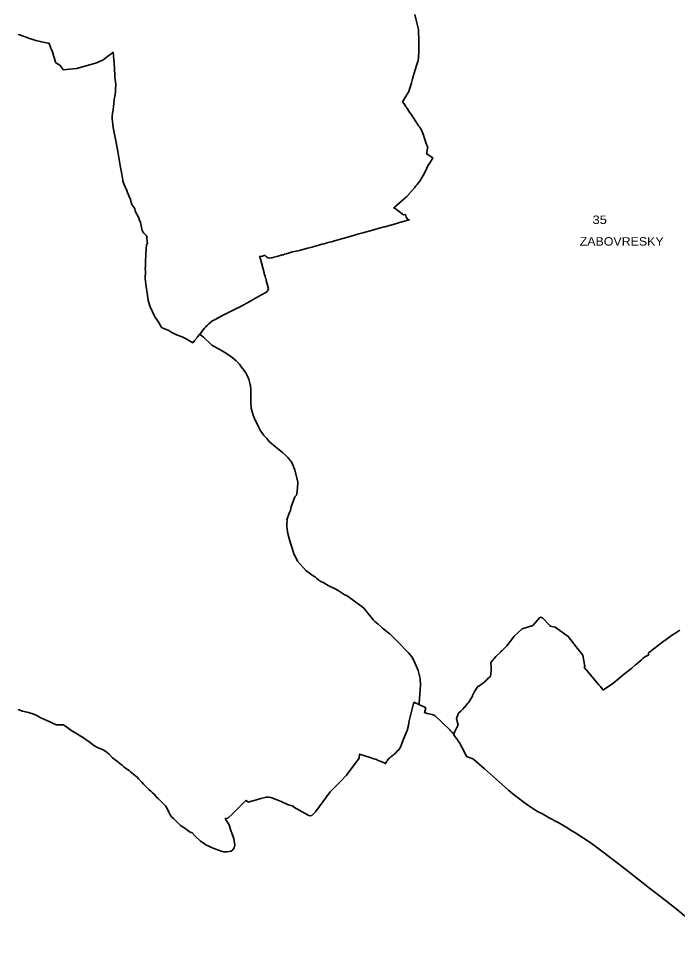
# Model space of a CAD drawing. Extents: x -610940 to -588976, y -1170376 to -1149800.
# Drawn here: x -602206 to -600249, y -1160526 to -1157770 of the extents above; entities that cross this region are included whole.
import ezdxf

# ---------------------------------------------------------------- set-up
doc = ezdxf.new("R2010")
doc.units = 0
doc.header["$LTSCALE"] = 10
doc.layers.add('54', color=7, linetype='Continuous', lineweight=35)
doc.layers.add('55', color=7, linetype='Continuous')
doc.layers.add('56', color=7, linetype='Continuous')

msp = doc.modelspace()

# ---------------------------------------------------------------- linework, layer by layer
at = {"layer": '54'}
for p, q in [((-600256.89, -1159594.38), (-600242.07, -1159585.3)), ((-600761.14, -1159636.5), (-600755.67, -1159631.06)), ((-600318.84, -1159639.11), (-600306.21, -1159629.48)), ((-600803.69, -1159681.2), (-600788.7, -1159663.5)), ((-600788.7, -1159663.5), (-600775.01, -1159650.19)), ((-600775.01, -1159650.19), (-600774.45, -1159649.64)), ((-600774.45, -1159649.64), (-600769.94, -1159645.18)), ((-600346.15, -1159664.1), (-600336.38, -1159659.02)), ((-600335.61, -1159654.46), (-600335.55, -1159653.86)), ((-600335.55, -1159653.86), (-600335.41, -1159653.29)), ((-600335.2, -1159652.76), (-600335.41, -1159653.29)), ((-600335.2, -1159652.76), (-600334.93, -1159652.27)), ((-600334.93, -1159652.27), (-600334.53, -1159651.75)), ((-600334.13, -1159651.34), (-600334.53, -1159651.75)), ((-600384.88, -1159697.23), (-600373.9, -1159688.12)), ((-600464.78, -1159759.14), (-600442.27, -1159744.24)), ((-600464.78, -1159759.14), (-600469.58, -1159763.19)), ((-600876.64, -1159807.7), (-600871.66, -1159801.73)), ((-600866.79, -1159795.54), (-600863.14, -1159789.05)), ((-600898.49, -1159830.42), (-600892.88, -1159824.83)), ((-600892.88, -1159824.83), (-600887.2, -1159819.14)), ((-600887.2, -1159819.14), (-600881.69, -1159813.64)), ((-600909.7, -1159901.75), (-600913.09, -1159895.14)), ((-600904.86, -1159907.75), (-600909.7, -1159901.75)), ((-600895.74, -1159920.66), (-600900.15, -1159914.02)), ((-600470.21, -1160243.42), (-600501.91, -1160220.12)), ((-600416, -1160285.12), (-600470.21, -1160243.42)), ((-600397.56, -1160299.41), (-600416, -1160285.12))]:
    msp.add_line(p, q, dxfattribs=at)
for points in [[(-601029.74, -1157758.56), (-601025.69, -1157774.47), (-601022.58, -1157786.7), (-601019.49, -1157798.83), (-601018.42, -1157803.03), (-601018.14, -1157814.11), (-601017.81, -1157827.13), (-601017.46, -1157841.15)], [(-602207, -1157817.24), (-602202.54, -1157818.76), (-602195.15, -1157821.26), (-602194.27, -1157821.58), (-602192.13, -1157822.29), (-602180.25, -1157826.63), (-602179.38, -1157826.95), (-602178.75, -1157827.18), (-602176.41, -1157828.03), (-602166.9, -1157831.54), (-602166.14, -1157831.49), (-602160.68, -1157833.52), (-602155.24, -1157834.82), (-602154.31, -1157835.04), (-602153.54, -1157835.23), (-602141.7, -1157838.07), (-602138.09, -1157838.94)], [(-602138.09, -1157838.94), (-602118.22, -1157843.5), (-602115.24, -1157844.18), (-602109.73, -1157858.46), (-602107.49, -1157864.27), (-602099.56, -1157888.35), (-602095.84, -1157899.63), (-602095.28, -1157901.35), (-602083.71, -1157908.5), (-602074.91, -1157920.41), (-602073.32, -1157922.56), (-602033.8, -1157918.16), (-601998.69, -1157908.55), (-601974.08, -1157901.25), (-601969.3, -1157899.83), (-601954.96, -1157893.04), (-601937.8, -1157879.58), (-601932.44, -1157875.37), (-601931.46, -1157874.61), (-601925.53, -1157869.96), (-601922.48, -1157903.68), (-601921.22, -1157917.89), (-601920.75, -1157924.87), (-601920.28, -1157931.99), (-601919.92, -1157944.69), (-601918.05, -1157956.51), (-601917.55, -1157967.5), (-601917.69, -1157978.93), (-601917.93, -1157989.72), (-601920.13, -1158000.1), (-601921.64, -1158010.6), (-601923.02, -1158022.44), (-601924.01, -1158030.93), (-601925.13, -1158041.26), (-601927.36, -1158050.84), (-601927.84, -1158058.99), (-601927.85, -1158067.25), (-601927.1, -1158075.33), (-601925.42, -1158093.35), (-601916.59, -1158137.77)], [(-601017.46, -1157841.15), (-601017.09, -1157855.84), (-601017.05, -1157857.4), (-601017.14, -1157869.11), (-601017.17, -1157872.59), (-601018.03, -1157880.29), (-601018.29, -1157882.64), (-601018.56, -1157885.13), (-601019.79, -1157896.14), (-601019.95, -1157897.6), (-601023.99, -1157909.35), (-601027.95, -1157922.27)], [(-601036.62, -1157949.06), (-601034.6, -1157942.09), (-601027.95, -1157922.27)], [(-601036.62, -1157949.06), (-601038.07, -1157956.91), (-601038.8, -1157960.85), (-601047.23, -1157986.25), (-601056.55, -1158002.11), (-601063.64, -1158014.18), (-601065.44, -1158017.04), (-601061.4, -1158023.1), (-601058.06, -1158028.12), (-601056.39, -1158030.63), (-601055.7, -1158031.66), (-601054.31, -1158033.77), (-601054.1, -1158034.07), (-601049.44, -1158041.06), (-601048.63, -1158042.28), (-601046.81, -1158045.01), (-601044.67, -1158048.23), (-601039.39, -1158056.16), (-601036.36, -1158060.7), (-601033.36, -1158065.2), (-601028.5, -1158072.52), (-601026.6, -1158075.36), (-601024.72, -1158078.18), (-601023.07, -1158080.64), (-601022.63, -1158081.27), (-601020.98, -1158083.71), (-601018.04, -1158088.1), (-601015.77, -1158091.48), (-601013.9, -1158094.25), (-601012.77, -1158095.93), (-601010.54, -1158099.25), (-601009.4, -1158100.95), (-601004.94, -1158113.68), (-600999.71, -1158128.61), (-600996.53, -1158137.7), (-600993.52, -1158146.3), (-600992.88, -1158148.14), (-600990.97, -1158153.58), (-600991.66, -1158154.79), (-600992.42, -1158159.73)], [(-601916.59, -1158137.77), (-601911.67, -1158164.66), (-601903.45, -1158212.24), (-601899.78, -1158231.84), (-601896.7, -1158249.78), (-601896.1, -1158251.65), (-601893.21, -1158260.86), (-601889.66, -1158269.84), (-601884.46, -1158280.53), (-601882.1, -1158287.26), (-601881.68, -1158288.24), (-601877.85, -1158298.23), (-601873.87, -1158306.89), (-601872.04, -1158315.55), (-601868.19, -1158324.26), (-601860.41, -1158333.99), (-601859.31, -1158341.44), (-601848.47, -1158361.66), (-601846.89, -1158367.94), (-601844.3, -1158375.23), (-601842.73, -1158380.24), (-601841.47, -1158384.77), (-601840.81, -1158389.9), (-601840.19, -1158395.01), (-601839.24, -1158399.33), (-601837.26, -1158403.12), (-601833.97, -1158406.55), (-601829.62, -1158411.13), (-601826.54, -1158414.7), (-601824.75, -1158417.37), (-601824.06, -1158420.31), (-601825.01, -1158420.54), (-601824.26, -1158432.81), (-601823.37, -1158438.91), (-601824.93, -1158439.67), (-601826.04, -1158440.18), (-601827.63, -1158469.85), (-601829.25, -1158492.02), (-601828.87, -1158492.4), (-601828.84, -1158507.72)], [(-600992.42, -1158159.73), (-600993.65, -1158168.83), (-600994.16, -1158171.37), (-600992.22, -1158172.62), (-600984.66, -1158177.48), (-600975.34, -1158183.46), (-600979.62, -1158190.73), (-600986.1, -1158200.51), (-600990.78, -1158207.56), (-600996.95, -1158220.77), (-600999.15, -1158225.48), (-601001.98, -1158230.46), (-601004.83, -1158235.48), (-601007.68, -1158240.5), (-601010.52, -1158245.5), (-601012.82, -1158249.55), (-601015.85, -1158253.66), (-601019.36, -1158258.38), (-601022.65, -1158262.8), (-601025.85, -1158266.97), (-601029.6, -1158271.44), (-601038.17, -1158281.69), (-601053.38, -1158298.48), (-601092.13, -1158332.24), (-601087.47, -1158334.21), (-601062.52, -1158352.45), (-601057.02, -1158351.88), (-601054.63, -1158359.48), (-601049.72, -1158366.17), (-601045.69, -1158367.32), (-601059.64, -1158371.1), (-601064.4, -1158372.64), (-601074.37, -1158375.34), (-601087.11, -1158378.96), (-601118.28, -1158387.76), (-601120.23, -1158388.29), (-601134.74, -1158392.26), (-601151.39, -1158396.8), (-601183.79, -1158406.01), (-601195.49, -1158409.28)], [(-601195.49, -1158409.28), (-601217.94, -1158415.79), (-601267.8, -1158429.58), (-601270.55, -1158430.58), (-601270.86, -1158430.64), (-601277.15, -1158432.29), (-601281.51, -1158433.44), (-601282.32, -1158433.66), (-601286.6, -1158434.81), (-601295.24, -1158437.21), (-601298.59, -1158438.12), (-601303.88, -1158439.56), (-601305.16, -1158439.91), (-601317.28, -1158443.59), (-601324.06, -1158445.47), (-601328.85, -1158446.8), (-601334.07, -1158448.25), (-601337.94, -1158449.2), (-601347.86, -1158451.94), (-601371.81, -1158458.64), (-601381.57, -1158460.47), (-601392.27, -1158462.56), (-601404.2, -1158466.34), (-601408.57, -1158467.46), (-601410.11, -1158467.94), (-601416.57, -1158469.74), (-601419.74, -1158470.78), (-601423.11, -1158471.71), (-601431.65, -1158474.04), (-601439.39, -1158476.16), (-601447.76, -1158478.45), (-601453.21, -1158479.95), (-601455.58, -1158480.33), (-601461.12, -1158480.67), (-601464.98, -1158479.85), (-601466.58, -1158478.96), (-601467.03, -1158478.75), (-601470.1, -1158476.85), (-601473.81, -1158472.8), (-601475.34, -1158473.2)], [(-601475.34, -1158473.2), (-601475.95, -1158473.36), (-601476.96, -1158473.63), (-601480.01, -1158474.43), (-601481.12, -1158474.72), (-601482.58, -1158475.02), (-601488.34, -1158476.23), (-601490.1, -1158476.68), (-601489, -1158480.62), (-601476.9, -1158524.92), (-601476.28, -1158527.1), (-601476.19, -1158527.44), (-601475.53, -1158529.52), (-601473.98, -1158535.03), (-601473.76, -1158535.83), (-601472.58, -1158539.88), (-601472.49, -1158540.2), (-601472, -1158541.89), (-601470.87, -1158545.77), (-601470.62, -1158546.62), (-601470.34, -1158547.59), (-601464.34, -1158568.25), (-601464.23, -1158571.48), (-601464.57, -1158573.89), (-601465.44, -1158576.36), (-601467.01, -1158578.81), (-601469.05, -1158580.93), (-601473.36, -1158584.3), (-601495.54, -1158596.2), (-601526.23, -1158613.39), (-601530.79, -1158615.93), (-601533.08, -1158617.22), (-601544.78, -1158623.47), (-601550.18, -1158626.19), (-601557.16, -1158629.69), (-601602.51, -1158652.41), (-601622.67, -1158662.73), (-601627.83, -1158665.69), (-601632.35, -1158668.27), (-601632.05, -1158668.76)], [(-601828.84, -1158507.72), (-601829.82, -1158509.53), (-601828.98, -1158520.76), (-601830.22, -1158541.69), (-601828.34, -1158557.98), (-601823.39, -1158591.9), (-601821.1, -1158606.32), (-601821.06, -1158606.65), (-601814.71, -1158625.09), (-601801.26, -1158654.97), (-601791.57, -1158669.41), (-601783.81, -1158683.23), (-601781.69, -1158686.93), (-601772.29, -1158690.56), (-601761.32, -1158694.68), (-601750.71, -1158701.63), (-601737.04, -1158708.23), (-601720.08, -1158714.44), (-601708.22, -1158720.92), (-601688.07, -1158732.1), (-601687.5, -1158731.78), (-601687.81, -1158731.53), (-601685.53, -1158728.38), (-601685.73, -1158728.23), (-601685.23, -1158727.71), (-601684.98, -1158727.86), (-601683.08, -1158725.53), (-601674.66, -1158715.06), (-601674.89, -1158714.92), (-601674.49, -1158714.43), (-601674.27, -1158714.59), (-601668.05, -1158706.92), (-601667.75, -1158707.19), (-601666.01, -1158708.63), (-601657.09, -1158715.85), (-601655.34, -1158717.23), (-601654.93, -1158717.55), (-601635.87, -1158735.34), (-601631.7, -1158738.84), (-601623.32, -1158744.36)], [(-601632.05, -1158668.76), (-601633.34, -1158669.54), (-601640.96, -1158675.78), (-601641.93, -1158676.59), (-601645.36, -1158679.48), (-601645.77, -1158679.88), (-601647.89, -1158682.83), (-601648.34, -1158682.38), (-601650.58, -1158685.52), (-601650.88, -1158685.33), (-601651.23, -1158685.72), (-601651.04, -1158685.93), (-601651.8, -1158686.8), (-601653.66, -1158689.13), (-601661.59, -1158699.02), (-601661.88, -1158698.89), (-601662.26, -1158699.3), (-601662.08, -1158699.55), (-601668.05, -1158706.92)], [(-601623.32, -1158744.36), (-601603.37, -1158754.74), (-601593.57, -1158760.73), (-601583.08, -1158767.65), (-601572.15, -1158775.46), (-601565.9, -1158780.45), (-601560.1, -1158785.83), (-601554.16, -1158791.82), (-601550.26, -1158796), (-601543.76, -1158804.27), (-601536.26, -1158814.62), (-601530.56, -1158823.09), (-601526.02, -1158831.26), (-601524.01, -1158835.84), (-601522.65, -1158840.19), (-601520.44, -1158848.15), (-601518.25, -1158856.35), (-601517.74, -1158858.59), (-601516.73, -1158871.36), (-601516.27, -1158879.29), (-601516.01, -1158889.8), (-601516.14, -1158912.09), (-601515.61, -1158921.62), (-601515.06, -1158926.47), (-601512.77, -1158936.87), (-601509.17, -1158946.66), (-601503, -1158962.1), (-601500.92, -1158966.69), (-601492.68, -1158983.87), (-601487.24, -1158993.03), (-601480.95, -1159002.78), (-601477.28, -1159007.46), (-601469.24, -1159016.66), (-601461.54, -1159025.06), (-601447.58, -1159036.75), (-601421.99, -1159057.7), (-601412.85, -1159066.01), (-601406.76, -1159072.31), (-601402.09, -1159077.77), (-601397.73, -1159083.04)], [(-601397.73, -1159083.04), (-601395.93, -1159085.75), (-601392.47, -1159092.34), (-601389.42, -1159099.55), (-601385.53, -1159110.55), (-601376.38, -1159145.18), (-601376.61, -1159148.3), (-601378.46, -1159173.69), (-601380.73, -1159184.25), (-601385.61, -1159189.66), (-601396.05, -1159218.67), (-601397.43, -1159223.55), (-601398.36, -1159229.64), (-601402.35, -1159237.67), (-601404.9, -1159244), (-601407.24, -1159251.46), (-601409.03, -1159258.47), (-601408.78, -1159260.76), (-601409.61, -1159266.7), (-601409.74, -1159271.63), (-601409.54, -1159277.35), (-601408.18, -1159285.46), (-601405.96, -1159297.95), (-601402.23, -1159313.37), (-601398.76, -1159326.66), (-601394.77, -1159339.01), (-601387.11, -1159361.65), (-601387.07, -1159361.74), (-601377.79, -1159380.04), (-601352.54, -1159407.75), (-601330.86, -1159423.91), (-601324.66, -1159427.78), (-601320.01, -1159431.15), (-601314.1, -1159436.08), (-601308.09, -1159440.1), (-601299.22, -1159444.78), (-601291.35, -1159449.34), (-601286.69, -1159451.96), (-601265.84, -1159462.74), (-601256.96, -1159467.4)], [(-601256.96, -1159467.4), (-601236.32, -1159480.84), (-601234.39, -1159481), (-601227.71, -1159485.21), (-601211.16, -1159496.96), (-601186.78, -1159514.33), (-601181.01, -1159520.05), (-601152.27, -1159555.2), (-601148.38, -1159558.74), (-601138.46, -1159567.22), (-601129.62, -1159575.02), (-601124.96, -1159578.83), (-601115.56, -1159586.7), (-601105.82, -1159594.53), (-601103.76, -1159596.07), (-601069.03, -1159630), (-601060.49, -1159639.09), (-601047.92, -1159652.46), (-601037.83, -1159664.24), (-601031.48, -1159676.58), (-601019.45, -1159704.98), (-601013.66, -1159728.81), (-601012.67, -1159747.71), (-601016.48, -1159800.45), (-601017.46, -1159805), (-601031.84, -1159798.08)], [(-600734, -1159603.17), (-600710.98, -1159581.26), (-600679.28, -1159571.08), (-600657.04, -1159546.31), (-600649.88, -1159548.13), (-600628.54, -1159571.47), (-600627.47, -1159573.15)], [(-600627.47, -1159573.15), (-600612.53, -1159576.1), (-600574.17, -1159603.34), (-600549.75, -1159634.19), (-600530.18, -1159659.5), (-600524.48, -1159692.41), (-600526.19, -1159695.54)], [(-600755.67, -1159631.06), (-600746.02, -1159618.14), (-600736.22, -1159605.28), (-600734, -1159603.17)], [(-600306.21, -1159629.48), (-600295.86, -1159621.51), (-600283.38, -1159612.88)], [(-600283.38, -1159612.88), (-600275.25, -1159607.05), (-600263.73, -1159599.23), (-600256.89, -1159594.38)], [(-600769.94, -1159645.18), (-600768.2, -1159643.47), (-600761.14, -1159636.5)], [(-600334.13, -1159651.34), (-600332.03, -1159649.81), (-600318.84, -1159639.11)], [(-600364.48, -1159680.31), (-600355.94, -1159672.69), (-600351.08, -1159668.42), (-600346.15, -1159664.1)], [(-600336.38, -1159659.02), (-600334.49, -1159657.96), (-600335.31, -1159656.07), (-600335.61, -1159654.46)], [(-600805.03, -1159722.01), (-600803.95, -1159713.46), (-600802.94, -1159704.86), (-600802.26, -1159699.07), (-600802.44, -1159696.68), (-600803.69, -1159681.2)], [(-600526.19, -1159695.54), (-600519.7, -1159703.32), (-600518.5, -1159704.78), (-600482.83, -1159746.66), (-600478.3, -1159752.17), (-600469.58, -1159763.19)], [(-600418.82, -1159724.28), (-600410.72, -1159717.83), (-600384.88, -1159697.23)], [(-600373.9, -1159688.12), (-600369.2, -1159684.22), (-600364.48, -1159680.31)], [(-600815.78, -1159731.95), (-600810.07, -1159726.43), (-600805.03, -1159722.01)], [(-600442.27, -1159744.24), (-600434.38, -1159737.5), (-600431.61, -1159735.21), (-600418.82, -1159724.28)], [(-600857.55, -1159778.95), (-600854.6, -1159772.89), (-600851.82, -1159766.79), (-600842.16, -1159752.34), (-600839.57, -1159750.59), (-600828.58, -1159743.16)], [(-600828.58, -1159743.16), (-600824.4, -1159740.35), (-600823.41, -1159739.38)], [(-600823.41, -1159739.38), (-600817.72, -1159733.84), (-600817.51, -1159733.64), (-600815.78, -1159731.95)], [(-600863.14, -1159789.05), (-600858.21, -1159780.41), (-600857.55, -1159778.95)], [(-601031.84, -1159798.08), (-601046.61, -1159858.11), (-601046.68, -1159858.53), (-601047.73, -1159867.32), (-601052.23, -1159882.16), (-601058.23, -1159896.81), (-601064.47, -1159912.88), (-601071.56, -1159931.6), (-601077.24, -1159939.51), (-601082.91, -1159945.21), (-601087.11, -1159949.49), (-601090.89, -1159953.29), (-601092.04, -1159954.22), (-601093.51, -1159955.49), (-601096.72, -1159958.17), (-601100.24, -1159961.14), (-601103.69, -1159964.04), (-601107.05, -1159966.85), (-601109.74, -1159969.7), (-601111.7, -1159972.39), (-601112.97, -1159974.31), (-601114.61, -1159977.39), (-601115.98, -1159980.63), (-601116.49, -1159980.36), (-601122.62, -1159977.68), (-601125.49, -1159976.26), (-601129.3, -1159974.79), (-601130.06, -1159974.35), (-601140.45, -1159970.41), (-601143.51, -1159968.79), (-601147.2, -1159967.96), (-601153.89, -1159965.7), (-601158.6, -1159964.14), (-601158.9, -1159964.02), (-601180.79, -1159956.72), (-601184.15, -1159955.57), (-601190.58, -1159953.48), (-601193.31, -1159952.58), (-601195.05, -1159964.91), (-601232.02, -1160015.59)], [(-601017.46, -1159805), (-601008.02, -1159809.62), (-600999.77, -1159813.65), (-600997.08, -1159814.97), (-601000.27, -1159829.88), (-600994.14, -1159831.42), (-600992.28, -1159831.7), (-600982.3, -1159834.36), (-600978.66, -1159835.33), (-600978.2, -1159835.47), (-600971.03, -1159837.64), (-600971.1, -1159838.1), (-600970.15, -1159838.31), (-600924.61, -1159881.87), (-600923.1, -1159883.3), (-600917.93, -1159888.34), (-600915.85, -1159890.29), (-600915.38, -1159890.69), (-600914.28, -1159891.75), (-600914.02, -1159893.44)], [(-600881.69, -1159813.64), (-600881.22, -1159813.18), (-600876.64, -1159807.7)], [(-600871.66, -1159801.73), (-600868.77, -1159798.29), (-600866.79, -1159795.54)], [(-602194.77, -1159825.57), (-602206.77, -1159820.46)], [(-601840.37, -1160036.15), (-601844.59, -1160031.15), (-601849.63, -1160025.82), (-601854.26, -1160021.53), (-601858.68, -1160017.52), (-601863.34, -1160013.48), (-601868.18, -1160009.5), (-601873.33, -1160005.25), (-601878.05, -1160001.7), (-601882.61, -1159998.18), (-601888.36, -1159994.1), (-601893.19, -1159990.12), (-601898.09, -1159985.89), (-601904.46, -1159981.33), (-601911.13, -1159975.73), (-601918.75, -1159969.6), (-601926.86, -1159963.33), (-601937.05, -1159953.23), (-601946.81, -1159944.43), (-601955.16, -1159939.65), (-601964.84, -1159936.14), (-601971.83, -1159933.44), (-601982.06, -1159927.35), (-601993.68, -1159918.21), (-602008.79, -1159906.86), (-602009.84, -1159906.23), (-602031.34, -1159893.29), (-602050.98, -1159881.38), (-602066.21, -1159869.8), (-602073.92, -1159866.08), (-602091.04, -1159865.43), (-602093.55, -1159865.41), (-602101.24, -1159862.88), (-602106.66, -1159860.24), (-602122.44, -1159853.05), (-602140.33, -1159845.03), (-602153.92, -1159836.74), (-602166.23, -1159832.1), (-602180.19, -1159828.7), (-602194.77, -1159825.57)], [(-600903.46, -1159856.34), (-600906.01, -1159847.28), (-600899.22, -1159831.15), (-600898.49, -1159830.42)], [(-600910.33, -1159885.55), (-600900.9, -1159865.4), (-600903.46, -1159856.34)], [(-600913.09, -1159895.14), (-600914.02, -1159893.44), (-600911.74, -1159888.54), (-600910.33, -1159885.55)], [(-600900.15, -1159914.02), (-600902.89, -1159910.43), (-600904.86, -1159907.75)], [(-600854.35, -1159968.35), (-600856.76, -1159966.6), (-600859.49, -1159965.96), (-600873.55, -1159961.12), (-600874.86, -1159960.44), (-600875.77, -1159959.22), (-600876.14, -1159958.5), (-600876.68, -1159957.48), (-600887.09, -1159937.45), (-600890.52, -1159930.61), (-600893.91, -1159924.14), (-600895.74, -1159920.66)], [(-600635.72, -1160138.3), (-600652.56, -1160129.19), (-600662.72, -1160123.6), (-600675.85, -1160115.7), (-600691.11, -1160106.01), (-600704.98, -1160096.5), (-600725.7, -1160080.66), (-600738.61, -1160070.32), (-600751.23, -1160059.36), (-600822.2, -1159996.83), (-600854.35, -1159968.35)], [(-601232.02, -1160015.59), (-601253.4, -1160037.01), (-601281.05, -1160064.82), (-601324.66, -1160124.17), (-601335.2, -1160134.68), (-601340.67, -1160135.49), (-601345.54, -1160134.05), (-601388.9, -1160109.68), (-601390.5, -1160107.34), (-601406.92, -1160101.86), (-601426.48, -1160093.35), (-601440.74, -1160087.62), (-601456.96, -1160081.22), (-601464.04, -1160080.46), (-601469.81, -1160080.11), (-601486.53, -1160084.27), (-601499.54, -1160088.02), (-601521.4, -1160094.39), (-601523.43, -1160094.92), (-601530.85, -1160089.84), (-601533.21, -1160092.46), (-601546.73, -1160106.17), (-601556.96, -1160115.91), (-601567.89, -1160126.67), (-601573.79, -1160132.48), (-601584.31, -1160142.83), (-601588.96, -1160143.48), (-601591.47, -1160143.82), (-601592.06, -1160143.91), (-601586.3, -1160153.18), (-601581.02, -1160162.99), (-601576.97, -1160176.26), (-601571.9, -1160190.24), (-601567.09, -1160203.52), (-601564.18, -1160222.56), (-601565.95, -1160230.89), (-601569.52, -1160236.61), (-601574.37, -1160240.18), (-601586.38, -1160242.62), (-601592.91, -1160242.56)], [(-601592.91, -1160242.56), (-601597.24, -1160242.24), (-601601.58, -1160241.26), (-601612.21, -1160237.4), (-601622.8, -1160233.79), (-601633.1, -1160229.88), (-601641.46, -1160225.85), (-601649.68, -1160221.41), (-601658.07, -1160216.12), (-601665.93, -1160210.64), (-601681.57, -1160195.99), (-601690.16, -1160186.56), (-601698.01, -1160183.18), (-601704.7, -1160178.5), (-601711.52, -1160173.54), (-601718.3, -1160168.85), (-601724.67, -1160164.37), (-601730.89, -1160158.48), (-601736.25, -1160153.86), (-601741.14, -1160148.79), (-601746.25, -1160143.53), (-601751.38, -1160138.35), (-601755.81, -1160132.99), (-601759.89, -1160125.24), (-601765.15, -1160114.43), (-601766.87, -1160111.04), (-601769.23, -1160106.37), (-601778.02, -1160097.78), (-601785.25, -1160090.4), (-601791.45, -1160084.44), (-601797.13, -1160079.13), (-601800.84, -1160075.06), (-601802.61, -1160072.87), (-601808.92, -1160066.97), (-601813.64, -1160062.6), (-601819.32, -1160057.19), (-601825.03, -1160052.02), (-601829.86, -1160047.13), (-601835.34, -1160041.41), (-601840.37, -1160036.15)], [(-600635.72, -1160138.3), (-600631.9, -1160140.38), (-600601.38, -1160157)], [(-600536.11, -1160196.78), (-600549.45, -1160188.1), (-600562.59, -1160179.85), (-600579.6, -1160169.74), (-600601.38, -1160157)], [(-600536.11, -1160196.78), (-600523.77, -1160205.21), (-600501.91, -1160220.12)], [(-600116.15, -1160526.25), (-600126.1, -1160520.21), (-600138.76, -1160511.76), (-600151.84, -1160502.25), (-600159.7, -1160496.34), (-600170.75, -1160487.14), (-600176.1, -1160482.15), (-600185.22, -1160473.25), (-600206.08, -1160453.49), (-600217.54, -1160442.6), (-600229.41, -1160431.52), (-600247.87, -1160415.66), (-600285.71, -1160385.84), (-600332.06, -1160350.1), (-600397.56, -1160299.41)]]:
    msp.add_lwpolyline(points, dxfattribs=at)

# ---------------------------------------------------------------- texts
at = {"layer": '55', "width": 1.1}
msp.add_text('ZABOVRESKY ', height=25, dxfattribs=at).set_placement((-600539.71, -1158443.9))
at = {"layer": '56', "width": 1.15}
msp.add_text('35 ', height=25, dxfattribs=at).set_placement((-600501.75, -1158379.73))

doc.saveas('drawing.dxf')
